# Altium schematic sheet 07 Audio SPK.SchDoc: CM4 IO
size 297 x 209 mm; Page Create Date: March  8, 1995; Page Number: 7; Page Size: A4; Comment: radxa_1010; Page Count: 19; RevCode: V1.10; Doc: 07 Audio SPK; DsnPath: D:\WMS\黄工\[RC126]CM4_IO_V1.10\[RC126]_V1.10\CM4 IO_V1.10.DSN; SchematicName: CM4 IO V1.10; PageName: 07 Audio SPK; PageSize: A4; TopSchematic: True
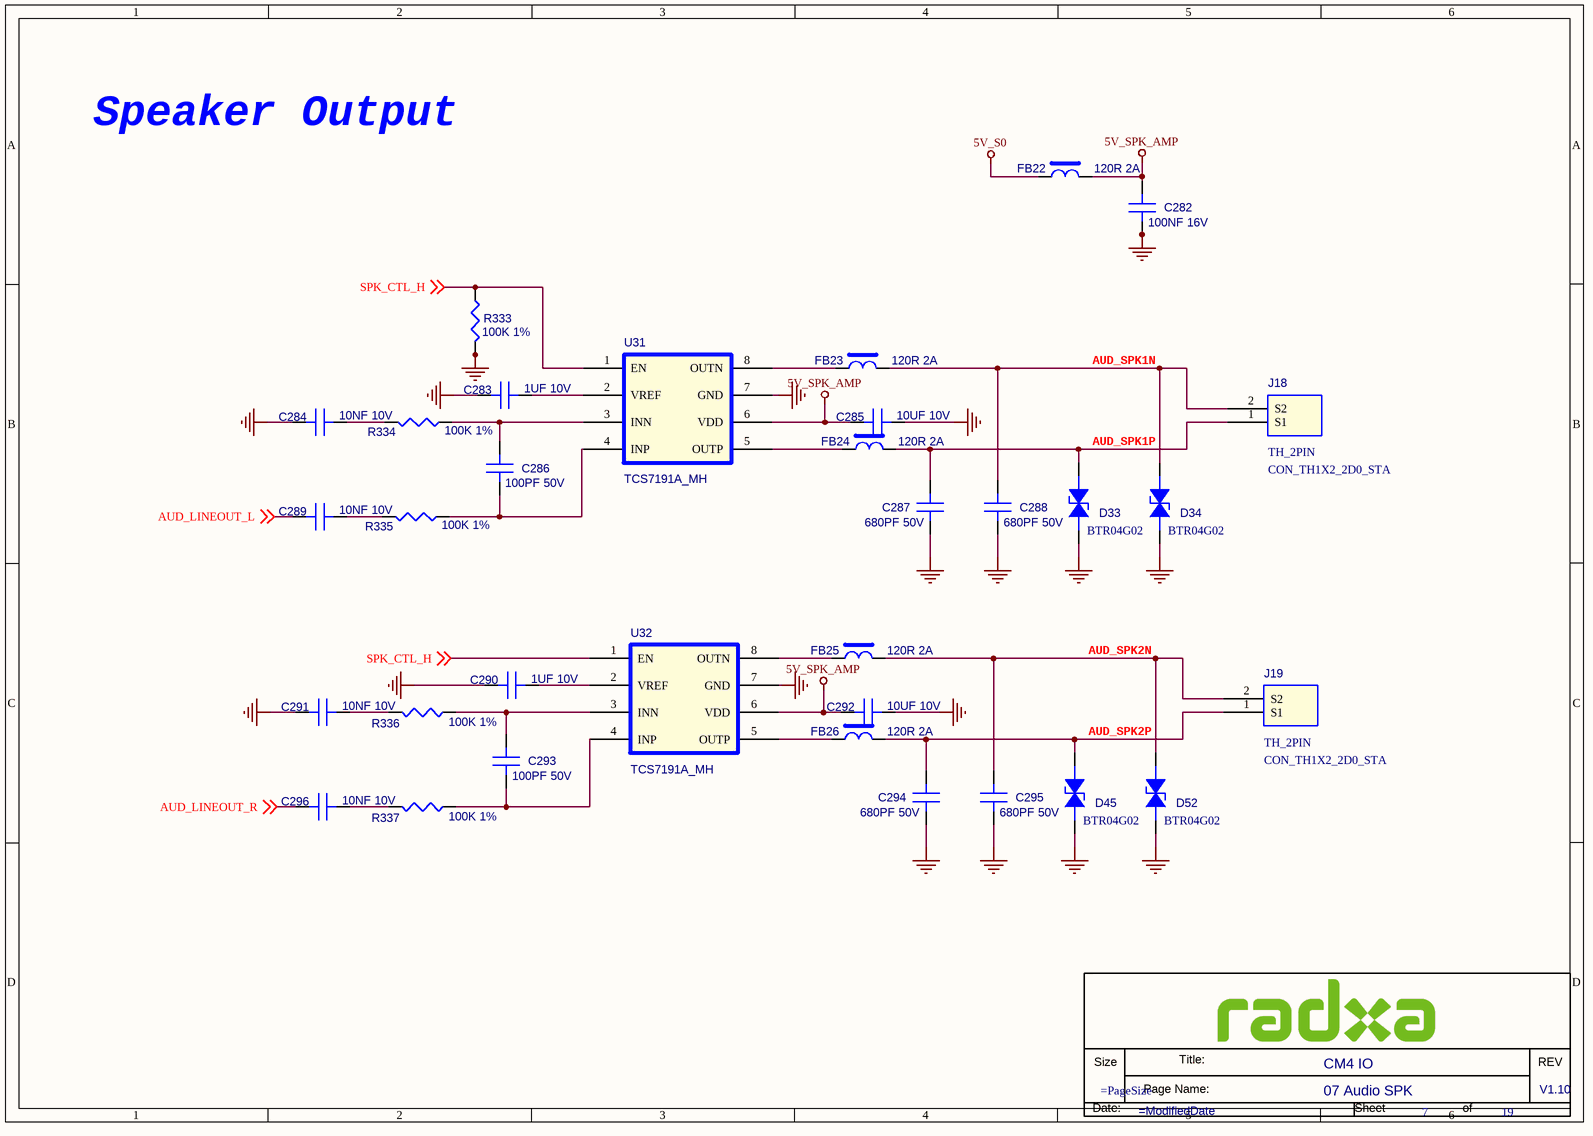
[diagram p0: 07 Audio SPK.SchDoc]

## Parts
*  Doc: 07 Audio SPK  RevCode: V1.10  Title: CM4 IO  Page Number: 7  Page Count: 19  (hidden comment: radxa_1010)  (graphical)
C282  100NF 16V  [C0201]
C283  1UF 10V  [C0201]
C284  10NF 10V  [C0201]
C285  10UF 10V  [C0603]
C286  100PF 50V  [C0201]
C287  680PF 50V  [C0201]
C288  680PF 50V  [C0201]
C289  10NF 10V  [C0201]
C290  1UF 10V  [C0201]
C291  10NF 10V  [C0201]
C292  10UF 10V  [C0603]
C293  100PF 50V  [C0201]
C294  680PF 50V  [C0201]
C295  680PF 50V  [C0201]
C296  10NF 10V  [C0201]
D33  BTR04G02  [DFN1006-2L]
D34  BTR04G02  [DFN1006-2L]
D45  BTR04G02  [DFN1006-2L]
D52  BTR04G02  [DFN1006-2L]
FB22  120R 2A  [FB0402]
FB23  120R 2A  [FB0402]
FB24  120R 2A  [FB0402]
FB25  120R 2A  [FB0402]
FB26  120R 2A  [FB0402]
J18  TH_2PIN  PCB Footprint: CON_TH1X2_2D0_STA  [CON_TH1X2_2D54_STA]
J19  TH_2PIN  PCB Footprint: CON_TH1X2_2D0_STA  [CON_TH1X2_2D54_STA]
R333  100K 1%  [R0402]
R334  100K 1%  [R0402]
R335  100K 1%  [R0402]
R336  100K 1%  [R0402]
R337  100K 1%  [R0402]
U31  TCS7191A_MH  [MSOP8_0D65_5D0]
U32  TCS7191A_MH  [MSOP8_0D65_5D0]

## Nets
5V_S0: FB22.1
5V_SPK_AMP: C282.1(A) C285.1(A) C292.1(A) FB22.2 U31.6(VDD) U32.6(VDD)
GND: C282.2(B) C283.1(A) C284.1(A) C285.2(B) C287.2(B) C288.2(B) C290.1(A) C291.1(A) C292.2(B) C294.2(B) C295.2(B) D33.1(ANODE) D34.1(ANODE) D45.1(ANODE) D52.1(ANODE) R333.2 U31.7(GND) U32.7(GND)
AUD_LINEOUT_L: C289.1(A) ; off-sheet AUD_LINEOUT_L
AUD_LINEOUT_R: C296.1(A) ; off-sheet AUD_LINEOUT_R
AUD_SPK1N: C288.1(A) D34.2(CATHODE) FB23.2 J18.2(S2)
AUD_SPK1P: C287.1(A) D33.2(CATHODE) FB24.2 J18.1(S1)
AUD_SPK2N: C295.1(A) D52.2(CATHODE) FB25.2 J19.2(S2)
AUD_SPK2P: C294.1(A) D45.2(CATHODE) FB26.2 J19.1(S1)
SPK_CTL_H: R333.1 U31.1(EN) U32.1(EN) ; off-sheet SPK_CTL_H
NetC283_2: C283.2(B) U31.2(VREF)
NetC284_2: C284.2(B) R334.1
NetC286_1: C286.1(A) R334.2 U31.3(INN)
NetC286_2: C286.2(B) R335.2 U31.4(INP)
NetC289_2: C289.2(B) R335.1
NetC290_2: C290.2(B) U32.2(VREF)
NetC291_2: C291.2(B) R336.1
NetC293_1: C293.1(A) R336.2 U32.3(INN)
NetC293_2: C293.2(B) R337.2 U32.4(INP)
NetC296_2: C296.2(B) R337.1
NetFB23_1: FB23.1 U31.8(OUTN)
NetFB24_1: FB24.1 U31.5(OUTP)
NetFB25_1: FB25.1 U32.8(OUTN)
NetFB26_1: FB26.1 U32.5(OUTP)

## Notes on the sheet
- Speaker Output

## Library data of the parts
C282 = C: SMD  0201  100NF  16V  X5R  ±20%  ROHS; PARTS: 1; Part Reference: C282; Part Number: A1C01.00099; OriginalSymbolOrigin: (0,30); PKG_TYPE: CAP2-100-250; LEVEL: STD; PINSWAP: (A,B); Preferred: 6715f349cd0bc5
C283 = C: SMD  0201  1UF  10V  X5R  ±20%  ROHS; PARTS: 1; Part Reference: C283; Part Number: A1C01.00081; OriginalSymbolOrigin: (0,30); PKG_TYPE: CAP2-100-250; LEVEL: STD; PINSWAP: (A,B)
C284 = C: SMD  0201  10NF  10V  X5R  ±20%  ROHS; PARTS: 1; Part Reference: C284; Part Number: A1C01.00095; OriginalSymbolOrigin: (0,30); PKG_TYPE: CAP2-100-250; LEVEL: STD; PINSWAP: (A,B)
C285 = C: SMD  0603  10UF  10V  X5R  ±20%  ROHS; PARTS: 1; Part Reference: C285; Part Number: A1C01.00075; OriginalSymbolOrigin: (0,30); PKG_TYPE: CAP2-100-250; LEVEL: STD; PINSWAP: (A,B)
C286 = C: SMD  0201  100PF  50V  NPO  ±5%  ROHS; PARTS: 1; Part Reference: C286; Part Number: A1C01.00382; OriginalSymbolOrigin: (0,30); PKG_TYPE: CAP2-100-250; LEVEL: STD; PINSWAP: (A,B)
C287 = C: SMD  0201  680PF  50V  X7R  ±10%  ROHS; PARTS: 1; Part Reference: C287; Part Number: A1C01.00071; OriginalSymbolOrigin: (0,30); PKG_TYPE: CAP2-100-250; LEVEL: STD; PINSWAP: (A,B)
C288 = C: SMD  0201  680PF  50V  X7R  ±10%  ROHS; PARTS: 1; Part Reference: C288; Part Number: A1C01.00071; OriginalSymbolOrigin: (0,30); PKG_TYPE: CAP2-100-250; LEVEL: STD; PINSWAP: (A,B)
C289 = C: SMD  0201  10NF  10V  X5R  ±20%  ROHS; PARTS: 1; Part Reference: C289; Part Number: A1C01.00095; OriginalSymbolOrigin: (0,30); PKG_TYPE: CAP2-100-250; LEVEL: STD; PINSWAP: (A,B)
C290 = C: SMD  0201  1UF  10V  X5R  ±20%  ROHS; PARTS: 1; Part Reference: C290; Part Number: A1C01.00081; OriginalSymbolOrigin: (0,30); PKG_TYPE: CAP2-100-250; LEVEL: STD; PINSWAP: (A,B)
C291 = C: SMD  0201  10NF  10V  X5R  ±20%  ROHS; PARTS: 1; Part Reference: C291; Part Number: A1C01.00095; OriginalSymbolOrigin: (0,30); PKG_TYPE: CAP2-100-250; LEVEL: STD; PINSWAP: (A,B)
C292 = C: SMD  0603  10UF  10V  X5R  ±20%  ROHS; PARTS: 1; Part Reference: C292; Part Number: A1C01.00075; OriginalSymbolOrigin: (0,30); PKG_TYPE: CAP2-100-250; LEVEL: STD; PINSWAP: (A,B)
C293 = C: SMD  0201  100PF  50V  NPO  ±5%  ROHS; PARTS: 1; Part Reference: C293; Part Number: A1C01.00382; OriginalSymbolOrigin: (0,30); PKG_TYPE: CAP2-100-250; LEVEL: STD; PINSWAP: (A,B)
C294 = C: SMD  0201  680PF  50V  X7R  ±10%  ROHS; PARTS: 1; Part Reference: C294; Part Number: A1C01.00071; OriginalSymbolOrigin: (0,30); PKG_TYPE: CAP2-100-250; LEVEL: STD; PINSWAP: (A,B)
C295 = C: SMD  0201  680PF  50V  X7R  ±10%  ROHS; PARTS: 1; Part Reference: C295; Part Number: A1C01.00071; OriginalSymbolOrigin: (0,30); PKG_TYPE: CAP2-100-250; LEVEL: STD; PINSWAP: (A,B)
C296 = C: SMD  0201  10NF  10V  X5R  ±20%  ROHS; PARTS: 1; Part Reference: C296; Part Number: A1C01.00095; OriginalSymbolOrigin: (0,30); PKG_TYPE: CAP2-100-250; LEVEL: STD; PINSWAP: (A,B)
D33 = ESD: SMD  编带  0402  BTR04G02  B-tron  ROHS; Part Reference: D33; Part Number: A1D02.00002; Parameter: ESD-台舟 ESD5341N-封装 esd0402; ID: DE-E0004; Temp Coeff: -50℃ ~ +125℃; PCB Footprint: ESD_D0402
D34 = ESD: SMD  编带  0402  BTR04G02  B-tron  ROHS; Part Reference: D34; Part Number: A1D02.00002; Parameter: ESD-台舟 ESD5341N-封装 esd0402; ID: DE-E0004; Temp Coeff: -50℃ ~ +125℃; PCB Footprint: ESD_D0402
D45 = ESD: SMD  编带  0402  BTR04G02  B-tron  ROHS; Part Reference: D45; Part Number: A1D02.00002; Parameter: ESD-台舟 ESD5341N-封装 esd0402; ID: DE-E0004; Temp Coeff: -50℃ ~ +125℃; PCB Footprint: ESD_D0402
D52 = ESD: SMD  编带  0402  BTR04G02  B-tron  ROHS; Part Reference: D52; Part Number: A1D02.00002; Parameter: ESD-台舟 ESD5341N-封装 esd0402; ID: DE-E0004; Temp Coeff: -50℃ ~ +125℃; PCB Footprint: ESD_D0402
FB22 = BEAD: SMD  0402  FB120R  2A  ±25%  ROHS; Part Reference: FB22; Part Number: A1L09.00004
FB23 = BEAD: SMD  0402  FB120R  2A  ±25%  ROHS; Part Reference: FB23; Part Number: A1L09.00004
FB24 = BEAD: SMD  0402  FB120R  2A  ±25%  ROHS; Part Reference: FB24; Part Number: A1L09.00004
FB25 = BEAD: SMD  0402  FB120R  2A  ±25%  ROHS; Part Reference: FB25; Part Number: A1L09.00004
FB26 = BEAD: SMD  0402  FB120R  2A  ±25%  ROHS; Part Reference: FB26; Part Number: A1L09.00004
J18 = TH_2PIN: DIP  排针座  1*2PIN  180度  2.0mm脚距  中间朔高2.0mm  针长一端3.9mm  另一端2.8mm  方针  黑色  ZX-PZ2.0-1-2PZZ  Megastar(兆星)  ROHS; Part Reference: J18; Part Number: A1J02.00089; Temp Coeff: -40℃ to +105℃; Preferred: 6715f352cd0bcd
J19 = TH_2PIN: DIP  排针座  1*2PIN  180度  2.0mm脚距  中间朔高2.0mm  针长一端3.9mm  另一端2.8mm  方针  黑色  ZX-PZ2.0-1-2PZZ  Megastar(兆星)  ROHS; Part Reference: J19; Part Number: A1J02.00089; Temp Coeff: -40℃ to +105℃; Preferred: 6715f352cd0bcd
R333 = R: SMD  0201  100K  1/20W  ±1%  ROHS; Part Reference: R333; Part Number: A1R01.00165; Preferred: 6715f349cd0bc5
R334 = R: SMD  0201  100K  1/20W  ±1%  ROHS; Part Reference: R334; Part Number: A1R01.00165; Preferred: 6715f349cd0bc5
R335 = R: SMD  0201  100K  1/20W  ±1%  ROHS; Part Reference: R335; Part Number: A1R01.00165; Preferred: 6715f349cd0bc5
R336 = R: SMD  0201  100K  1/20W  ±1%  ROHS; Part Reference: R336; Part Number: A1R01.00165; Preferred: 6715f349cd0bc5
R337 = R: SMD  0201  100K  1/20W  ±1%  ROHS; Part Reference: R337; Part Number: A1R01.00165; Preferred: 6715f349cd0bc5
U31 = TCS7191A_MH: SMD  音频功率放大器  TCS7191A_MH  MSOP-8  TCS(汤诚)  ROHS; Part Reference: U31; Part Number: A1I01.00891; Preferred: 6715f349cd0bc5; Temp Coeff: -40℃ to +85℃
U32 = TCS7191A_MH: SMD  音频功率放大器  TCS7191A_MH  MSOP-8  TCS(汤诚)  ROHS; Part Reference: U32; Part Number: A1I01.00891; Preferred: 6715f349cd0bc5; Temp Coeff: -40℃ to +85℃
